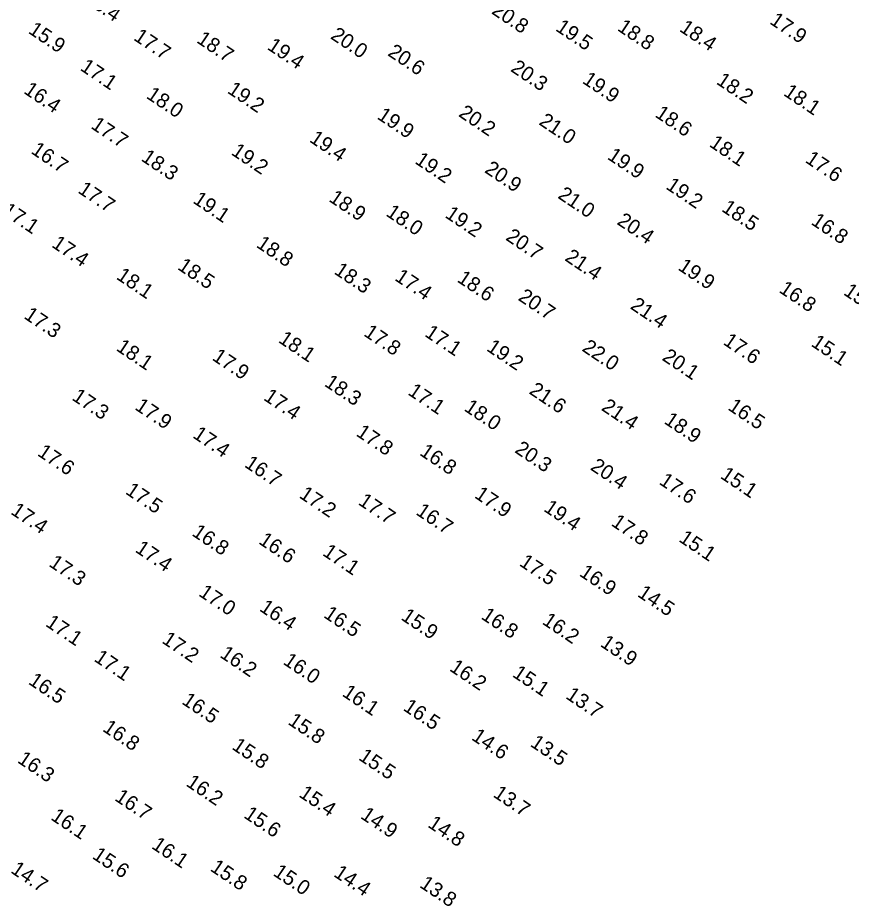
# Model space of a CAD drawing. Extents: x 815352 to 820877, y 582403 to 597439.
# Drawn here: x 817084.3 to 817369.3, y 584623.2 to 584926.9 of the extents above; entities that cross this region are included whole.
import ezdxf

# ---------------------------------------------------------------- set-up
doc = ezdxf.new("R2010")
doc.units = 0
doc.layers.add('V-TOPO-SOUN', color=7, linetype='Continuous')

msp = doc.modelspace()

# ---------------------------------------------------------------- texts
at = {"layer": 'V-TOPO-SOUN'}
for s, p in [('16.4 ', (817106.67, 584932.62)), ('20.8 ', (817246.01, 584928.55)), ('17.9 ', (817341.09, 584925.11)), ('19.5 ', (817267.89, 584922.75)), ('18.8 ', (817289.02, 584922.81)), ('18.4 ', (817310.25, 584922.55)), ('15.9 ', (817087.64, 584921.89)), ('17.7 ', (817123.64, 584919.56)), ('20.0 ', (817190.96, 584920.03)), ('18.7 ', (817145.19, 584918.68)), ('19.4 ', (817169.3, 584916.38)), ('20.6 ', (817210.51, 584914.24)), ('17.1 ', (817105.36, 584909.24)), ('20.3 ', (817252.54, 584908.87)), ('19.9 ', (817277.05, 584904.83)), ('18.2 ', (817322.85, 584904.54)), ('16.4 ', (817086.07, 584901.35)), ('19.2 ', (817155.69, 584901.45)), ('18.0 ', (817127.97, 584899.69)), ('18.1 ', (817345.81, 584900.61)), ('19.9 ', (817206.87, 584892.63)), ('20.2 ', (817234.72, 584893.45)), ('18.6 ', (817301.88, 584893.28)), ('17.7 ', (817109.04, 584889.38)), ('21.0 ', (817262.19, 584890.64)), ('19.4 ', (817183.74, 584884.75)), ('18.1 ', (817320.42, 584883.16)), ('16.7 ', (817088.56, 584880.82)), ('19.2 ', (817157, 584880.36)), ('18.3 ', (817126.23, 584878.29)), ('19.2 ', (817219.8, 584877.37)), ('19.9 ', (817285.58, 584878.85)), ('17.6 ', (817353.23, 584877.73)), ('20.9 ', (817243.62, 584874.29)), ('19.2 ', (817305.59, 584868.68)), ('17.7 ', (817104.61, 584867.33)), ('18.9 ', (817190.4, 584864.41)), ('21.0 ', (817268.65, 584865.51)), ('19.1 ', (817143.91, 584863.87)), ('17.1 ', (817078.65, 584860.03)), ('18.0 ', (817209.89, 584859.47)), ('19.2 ', (817230.1, 584858.9)), ('18.5 ', (817324.65, 584861.03)), ('20.4 ', (817288.89, 584856.57)), ('16.8 ', (817355.23, 584856.54)), ('20.7 ', (817250.83, 584851.19)), ('17.4 ', (817095.62, 584848.8)), ('18.8 ', (817165.56, 584848.76)), ('21.4 ', (817271.04, 584844.17)), ('18.5 ', (817138.66, 584841.15)), ('19.9 ', (817309.72, 584840.99)), ('18.1 ', (817117.73, 584837.85)), ('18.3 ', (817192.17, 584839.64)), ('17.4 ', (817212.91, 584837.41)), ('18.6 ', (817234.23, 584836.91)), ('20.7 ', (817255.1, 584830.62)), ('16.8 ', (817344.27, 584833.31)), ('15.4 ', (817366.32, 584832.49)), ('21.4 ', (817293.42, 584827.7)), ('17.3 ', (817086.14, 584824.39)), ('18.1 ', (817173.14, 584816.19)), ('17.8 ', (817202.31, 584818.45)), ('17.1 ', (817223.14, 584818.29)), ('18.1 ', (817117.66, 584813.44)), ('19.2 ', (817244.27, 584813.36)), ('22.0 ', (817276.92, 584813.28)), ('17.6 ', (817325.18, 584815.49)), ('15.1 ', (817355.22, 584814.95)), ('17.9 ', (817150.47, 584810.18)), ('20.1 ', (817304.31, 584810.13)), ('18.3 ', (817188.86, 584801.29)), ('17.1 ', (817217.4, 584798.31)), ('21.6 ', (817258.84, 584798.66)), ('17.3 ', (817102.54, 584796.53)), ('17.4 ', (817168.06, 584796.5)), ('17.9 ', (817124.06, 584793.25)), ('18.0 ', (817236.6, 584792.84)), ('21.4 ', (817283.54, 584793.02)), ('16.5 ', (817326.78, 584793.15)), ('18.9 ', (817305, 584788.46)), ('17.4 ', (817143.85, 584783.61)), ('17.8 ', (817199.69, 584784.26)), ('17.6 ', (817090.76, 584777.5)), ('16.8 ', (817221.4, 584777.67)), ('20.3 ', (817253.92, 584778.55)), ('16.7 ', (817161.53, 584773.63)), ('20.4 ', (817279.77, 584772.65)), ('17.6 ', (817303.29, 584767.72)), ('15.1 ', (817324.22, 584769.77)), ('17.5 ', (817120.85, 584764.41)), ('17.2 ', (817180.23, 584763.1)), ('17.9 ', (817240.17, 584763.07)), ('17.7 ', (817200.44, 584760.74)), ('19.4 ', (817263.83, 584758.51)), ('17.4 ', (817081.64, 584757.52)), ('16.7 ', (817220.16, 584757.33)), ('17.8 ', (817286.92, 584753.55)), ('16.8 ', (817143.58, 584750.14)), ('16.6 ', (817166.38, 584747.38)), ('15.1 ', (817310.01, 584748.12)), ('17.4 ', (817124.16, 584744.56)), ('17.1 ', (817188.23, 584743.39)), ('17.5 ', (817255.49, 584739.87)), ('17.3 ', (817094.67, 584739.67)), ('16.9 ', (817276, 584736.39)), ('17.0 ', (817145.88, 584729.55)), ('14.5 ', (817295.88, 584729.34)), ('16.4 ', (817166.65, 584724.42)), ('16.5 ', (817188.6, 584722.19)), ('16.8 ', (817242.43, 584721.7)), ('17.1 ', (817093.51, 584719.21)), ('15.9 ', (817215.04, 584721.4)), ('16.2 ', (817263.33, 584719.92)), ('17.2 ', (817133.31, 584713.46)), ('13.9 ', (817283.18, 584712.28)), ('17.1 ', (817110.11, 584707.24)), ('16.2 ', (817153.13, 584708.57)), ('16.0 ', (817174.75, 584706.19)), ('16.2 ', (817231.64, 584703.95)), ('15.1 ', (817253.13, 584701.92)), ('16.5 ', (817087.68, 584699.39)), ('16.1 ', (817194.92, 584695.33)), ('13.7 ', (817271.34, 584694.47)), ('16.5 ', (817140.11, 584692.63)), ('16.5 ', (817215.76, 584690.43)), ('15.8 ', (817176.39, 584685.64)), ('16.8 ', (817113.04, 584683.31)), ('14.6 ', (817239.15, 584680.35)), ('15.8 ', (817157.23, 584677.14)), ('13.5 ', (817259.23, 584678.13)), ('15.5 ', (817200.54, 584673.5)), ('16.3 ', (817083.94, 584672.55)), ('16.2 ', (817141.55, 584664.58)), ('15.4 ', (817180.13, 584660.87)), ('13.7 ', (817246.54, 584660.84)), ('16.7 ', (817117.17, 584659.62)), ('16.1 ', (817095.32, 584653.04)), ('15.6 ', (817161.3, 584653.71)), ('14.9 ', (817201.23, 584653.49)), ('14.8 ', (817224.19, 584650.53)), ('16.1 ', (817129.77, 584643.23)), ('15.6 ', (817109.49, 584639.77)), ('14.7 ', (817081.64, 584634.89)), ('15.8 ', (817149.82, 584635.57)), ('15.0 ', (817171.34, 584633.95)), ('14.4 ', (817192.04, 584633.64)), ('13.8 ', (817221.4, 584629.93))]:
    msp.add_text(s, height=5, rotation=326, dxfattribs=at).set_placement(p)

doc.saveas('drawing.dxf')
